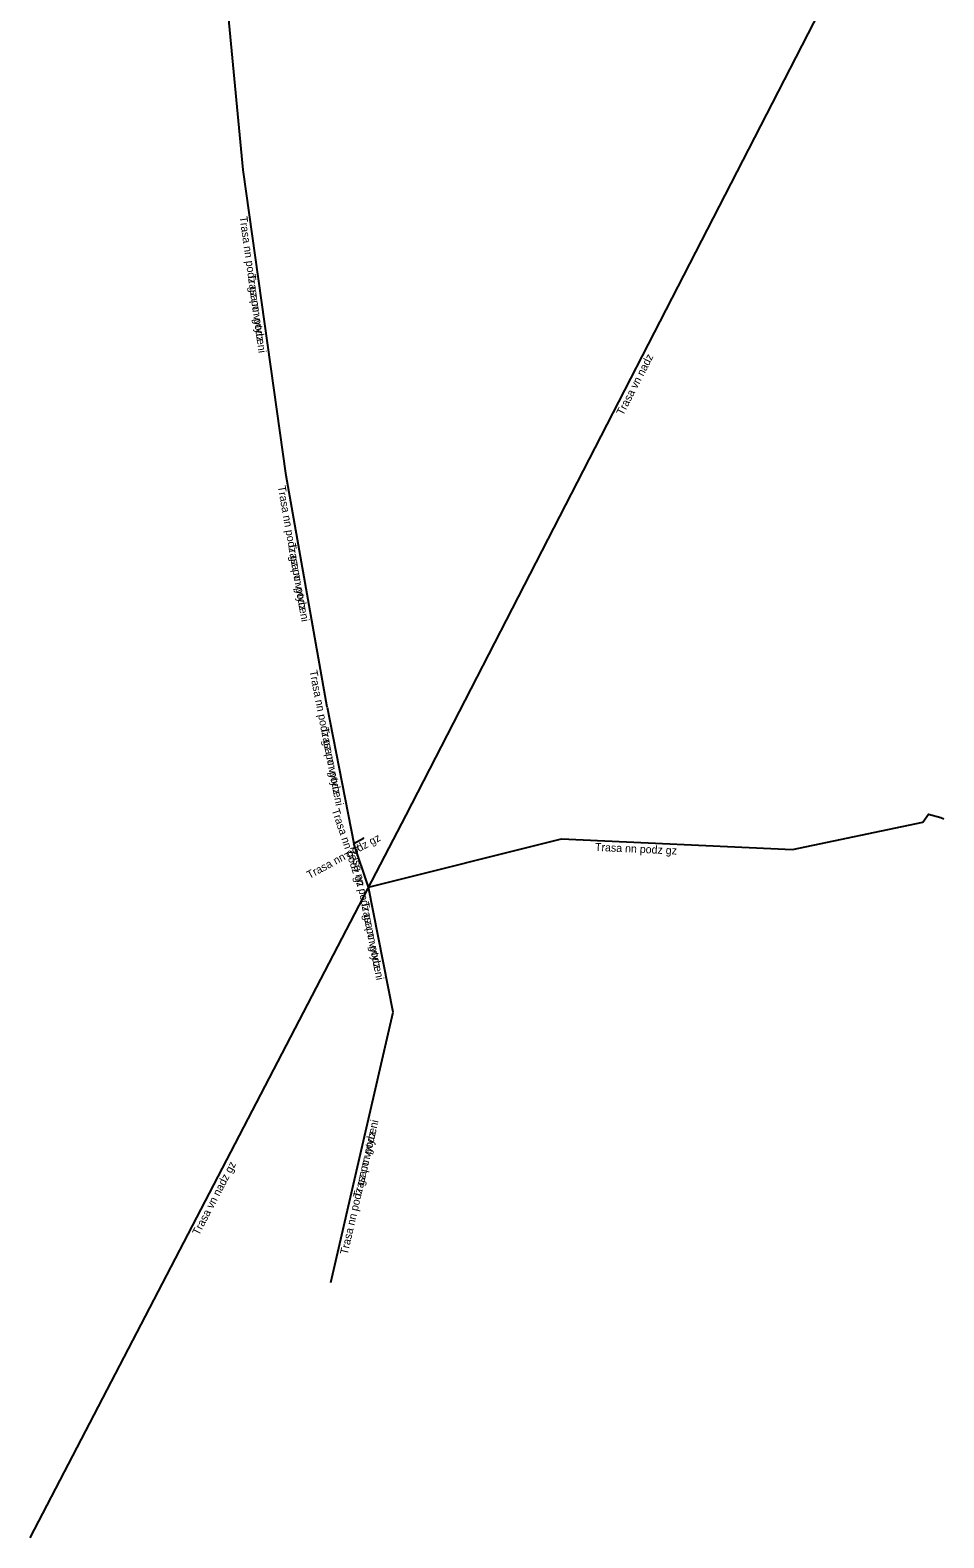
# Model space of a CAD drawing. Extents: x -632208 to -631919, y -1083193 to -1082791.
# Drawn here: x -632101.7 to -632044.1, y -1083193.5 to -1083098.4 of the extents above; entities that cross this region are included whole.
import ezdxf

# ---------------------------------------------------------------- set-up
doc = ezdxf.new("R2010")
doc.units = 0
for name, color, linetype in [('Popiskový text - Ostatní atributy Trasy', 7, 'Continuous'), ('Spojnice NN', 7, 'Continuous'), ('Spojnice VN', 7, 'Continuous')]:
    doc.layers.add(name, color=color, linetype=linetype)

msp = doc.modelspace()

# ---------------------------------------------------------------- linework, layer by layer
at = {"layer": 'Spojnice NN'}
for points in [[(-632088.29, -1083107.18), (-632090.71, -1083081.78)], [(-632088.29, -1083107.18), (-632090.71, -1083081.78)], [(-632085.58, -1083126.45), (-632088.29, -1083107.18)], [(-632085.58, -1083126.45), (-632088.29, -1083107.18)], [(-632083.01, -1083141.07), (-632085.58, -1083126.45)], [(-632083.01, -1083141.07), (-632085.58, -1083126.45)], [(-632083.01, -1083141.07), (-632081.33, -1083149.66)], [(-632083.01, -1083141.07), (-632081.33, -1083149.66)], [(-632080.4, -1083152.42), (-632068.23, -1083149.38), (-632053.67, -1083150.05), (-632045.45, -1083148.32), (-632045.1, -1083147.82), (-632044.33, -1083148.02), (-632044.133, -1083148.116)], [(-632081.33, -1083149.66), (-632080.72, -1083149.33), (-632080.73, -1083149.288)], [(-632080.4, -1083152.42), (-632081.33, -1083149.66)], [(-632078.84, -1083160.3), (-632080.4, -1083152.42)], [(-632078.84, -1083160.3), (-632080.4, -1083152.42)], [(-632082.78, -1083177.36), (-632078.84, -1083160.3)], [(-632082.78, -1083177.36), (-632078.84, -1083160.3)]]:
    msp.add_lwpolyline(points, dxfattribs=at)
at = {"layer": 'Spojnice VN'}
for points in [[(-632078.02, -1083147.88), (-632048.967, -1083091.346)], [(-632101.72, -1083193.46), (-632078.02, -1083147.88)]]:
    msp.add_lwpolyline(points, dxfattribs=at)

# ---------------------------------------------------------------- texts
at = {"layer": 'Popiskový text - Ostatní atributy Trasy'}
for s, rotation, p in [('Trasa nn podz gz po vytyceni', 278.00518, (-632088.53, -1083110.14)), ('Trasa nn podz', 278.00518, (-632088.017, -1083113.789)), ('Trasa vn nadz', 62.80123, (-632064.354, -1083122.71)), ('Trasa nn podz gz po vytyceni', 279.96997, (-632086.118, -1083127.143)), ('Trasa nn podz', 279.96997, (-632085.48, -1083130.772)), ('Trasa nn podz gz po vytyceni', 281.06601, (-632084.12, -1083138.784)), ('Trasa nn podz', 281.06601, (-632083.413, -1083142.401)), ('Trasa nn podz gz', 288.62158, (-632082.724, -1083147.558)), ('Trasa nn podz gz', 28.41266, (-632084.122, -1083151.91)), ('Trasa nn podz gz po vytyceni', 281.19803, (-632081.584, -1083149.784)), ('Trasa nn podz gz', 357.36531, (-632066.127, -1083150.128)), ('Trasa nn podz', 281.19803, (-632080.869, -1083153.399)), ('Trasa nn podz gz po vytyceni', 76.99557, (-632081.714, -1083175.634)), ('Trasa nn podz', 76.99557, (-632080.885, -1083172.043)), ('Trasa vn nadz gz', 62.52715, (-632091.089, -1083174.425))]:
    msp.add_text(s, height=0.5, rotation=rotation, dxfattribs=at).set_placement(p)

doc.saveas('drawing.dxf')
